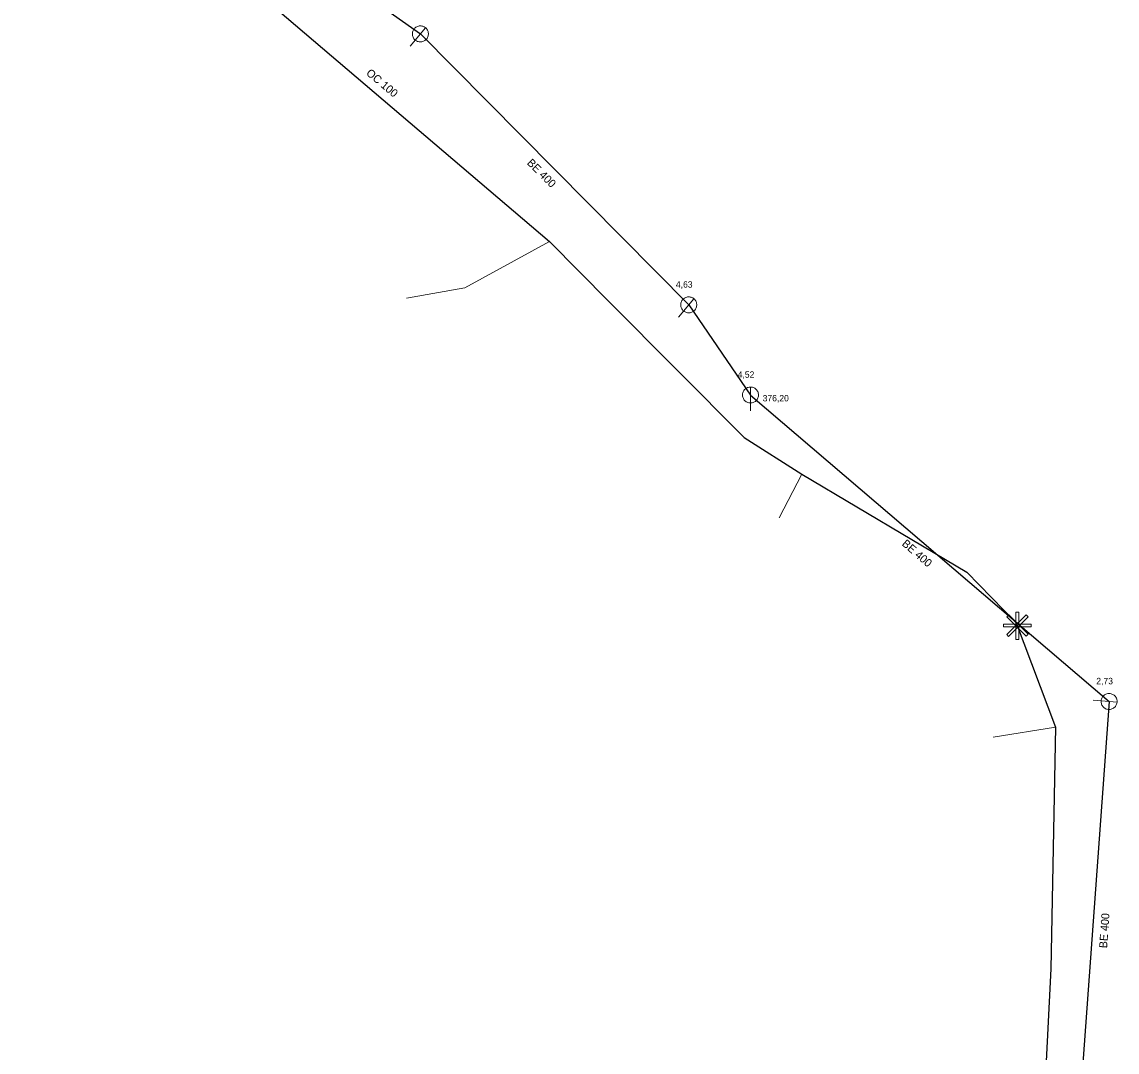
# Model space of a CAD drawing. Extents: x -809028 to -807737, y -990545 to -989489.
# Drawn here: x -808473.6 to -808336.8, y -990207.9 to -990079 of the extents above; entities that cross this region are included whole.
import ezdxf

# ---------------------------------------------------------------- set-up
doc = ezdxf.new("R2010")
doc.units = 0
doc.header["$LTSCALE"] = 0.32
for name, color, linetype, lineweight in [('1', 7, 'Continuous', 13), ('12', 7, 'Continuous', 13), ('13', 7, 'Continuous', 13), ('14', 7, 'Continuous', 25), ('17', 7, 'Continuous', 25), ('22', 7, 'Continuous', 13)]:
    doc.layers.add(name, color=color, linetype=linetype, lineweight=lineweight)

msp = doc.modelspace()

# ---------------------------------------------------------------- linework, layer by layer
at = {"layer": '12'}
for points in [[(-808348.121, -990153.189), (-808347.873, -990153.437), (-808350.302, -990155.866), (-808350.549, -990155.618)], [(-808350.54, -990153.428), (-808350.293, -990153.18), (-808347.864, -990155.609), (-808348.111, -990155.857)], [(-808349.387, -990152.825), (-808349.037, -990152.825), (-808349.037, -990156.26), (-808349.387, -990156.26)], [(-808347.503, -990154.334), (-808347.503, -990154.684), (-808350.938, -990154.684), (-808350.938, -990154.334)]]:
    msp.add_lwpolyline(points, close=True, dxfattribs=at)
at = {"layer": '13'}
for p, q in [((-808376.145, -990135.581), (-808379.004, -990141.028)), ((-808344.447, -990167.226), (-808352.252, -990168.485))]:
    msp.add_line(p, q, dxfattribs=at)
msp.add_lwpolyline([(-808407.697, -990106.489), (-808418.272, -990112.293), (-808425.572, -990113.592)], dxfattribs=at)
at = {"layer": '14'}
for p, q in [((-808423.829, -990080.539), (-808390.289, -990114.42)), ((-808337.75, -990164.01), (-808341.785, -990219.498))]:
    msp.add_line(p, q, dxfattribs=at)
for points in [[(-808473.629, -990044.855), (-808466.725, -990050.28), (-808423.829, -990080.539)], [(-808390.289, -990114.42), (-808382.57, -990125.69), (-808337.75, -990164.01)]]:
    msp.add_lwpolyline(points, dxfattribs=at)
at = {"layer": '17'}
msp.add_lwpolyline([(-808450.392, -990070.058), (-808407.697, -990106.489), (-808400.245, -990114.046), (-808383.377, -990131.011), (-808376.145, -990135.581), (-808355.548, -990147.837), (-808349.357, -990154.173), (-808344.447, -990167.226), (-808345.032, -990197.443), (-808345.713, -990210.651)], dxfattribs=at)
at = {"layer": '22'}
for p, q in [((-808425.116, -990082.069), (-808423.185, -990079.774)), ((-808391.577, -990115.95), (-808389.645, -990113.655)), ((-808382.57, -990127.69), (-808382.569, -990124.69)), ((-808339.744, -990163.858), (-808336.753, -990164.085))]:
    msp.add_line(p, q, dxfattribs=at)
for points in [[(-808423.064, -990081.183), (-808422.998, -990081.095), (-808422.942, -990081.001), (-808422.897, -990080.901), (-808422.863, -990080.798), (-808422.84, -990080.69), (-808422.829, -990080.581), (-808422.831, -990080.471), (-808422.845, -990080.363), (-808422.87, -990080.256), (-808422.906, -990080.153), (-808422.954, -990080.055), (-808423.013, -990079.962), (-808423.08, -990079.876), (-808423.157, -990079.798), (-808423.243, -990079.729), (-808423.335, -990079.67), (-808423.433, -990079.62), (-808423.535, -990079.582), (-808423.642, -990079.557), (-808423.749, -990079.542), (-808423.86, -990079.539), (-808423.968, -990079.549), (-808424.076, -990079.57), (-808424.181, -990079.603), (-808424.281, -990079.647), (-808424.375, -990079.702), (-808424.464, -990079.767), (-808424.544, -990079.84), (-808424.616, -990079.923), (-808424.679, -990080.013), (-808424.732, -990080.109), (-808424.773, -990080.21), (-808424.803, -990080.315), (-808424.823, -990080.423), (-808424.829, -990080.533), (-808424.824, -990080.642), (-808424.806, -990080.75), (-808424.777, -990080.856), (-808424.737, -990080.957), (-808424.686, -990081.054), (-808424.625, -990081.145), (-808424.554, -990081.228), (-808424.473, -990081.303), (-808424.386, -990081.369), (-808424.292, -990081.425), (-808424.193, -990081.47), (-808424.088, -990081.504), (-808423.981, -990081.527), (-808423.872, -990081.538), (-808423.763, -990081.537), (-808423.654, -990081.524), (-808423.547, -990081.498), (-808423.444, -990081.462), (-808423.346, -990081.414), (-808423.253, -990081.357), (-808423.167, -990081.288), (-808423.089, -990081.211)], [(-808389.524, -990115.064), (-808389.458, -990114.976), (-808389.402, -990114.882), (-808389.357, -990114.782), (-808389.323, -990114.679), (-808389.3, -990114.571), (-808389.289, -990114.462), (-808389.291, -990114.352), (-808389.305, -990114.244), (-808389.329, -990114.137), (-808389.366, -990114.035), (-808389.414, -990113.936), (-808389.473, -990113.843), (-808389.54, -990113.757), (-808389.617, -990113.679), (-808389.703, -990113.61), (-808389.794, -990113.551), (-808389.892, -990113.501), (-808389.995, -990113.463), (-808390.102, -990113.438), (-808390.209, -990113.423), (-808390.32, -990113.42), (-808390.428, -990113.43), (-808390.536, -990113.451), (-808390.641, -990113.484), (-808390.74, -990113.528), (-808390.835, -990113.583), (-808390.924, -990113.648), (-808391.004, -990113.721), (-808391.076, -990113.804), (-808391.139, -990113.894), (-808391.192, -990113.989), (-808391.233, -990114.091), (-808391.263, -990114.196), (-808391.282, -990114.304), (-808391.289, -990114.414), (-808391.284, -990114.523), (-808391.266, -990114.631), (-808391.237, -990114.736), (-808391.197, -990114.838), (-808391.146, -990114.935), (-808391.085, -990115.026), (-808391.014, -990115.109), (-808390.933, -990115.184), (-808390.846, -990115.25), (-808390.752, -990115.306), (-808390.653, -990115.351), (-808390.548, -990115.385), (-808390.441, -990115.408), (-808390.332, -990115.419), (-808390.223, -990115.418), (-808390.114, -990115.405), (-808390.008, -990115.379), (-808389.904, -990115.343), (-808389.806, -990115.295), (-808389.713, -990115.238), (-808389.627, -990115.169), (-808389.549, -990115.092)], [(-808381.57, -990125.69), (-808381.575, -990125.581), (-808381.593, -990125.473), (-808381.623, -990125.367), (-808381.663, -990125.266), (-808381.715, -990125.169), (-808381.777, -990125.079), (-808381.849, -990124.996), (-808381.929, -990124.922), (-808382.017, -990124.856), (-808382.111, -990124.801), (-808382.211, -990124.756), (-808382.316, -990124.723), (-808382.423, -990124.701), (-808382.532, -990124.691), (-808382.642, -990124.693), (-808382.75, -990124.707), (-808382.857, -990124.732), (-808382.96, -990124.769), (-808383.058, -990124.818), (-808383.15, -990124.876), (-808383.236, -990124.945), (-808383.313, -990125.022), (-808383.382, -990125.108), (-808383.441, -990125.2), (-808383.489, -990125.298), (-808383.526, -990125.401), (-808383.552, -990125.508), (-808383.566, -990125.616), (-808383.569, -990125.726), (-808383.559, -990125.835), (-808383.538, -990125.942), (-808383.504, -990126.046), (-808383.46, -990126.146), (-808383.405, -990126.241), (-808383.339, -990126.329), (-808383.265, -990126.409), (-808383.182, -990126.481), (-808383.092, -990126.543), (-808382.996, -990126.595), (-808382.894, -990126.636), (-808382.789, -990126.666), (-808382.681, -990126.684), (-808382.571, -990126.69), (-808382.462, -990126.684), (-808382.354, -990126.666), (-808382.249, -990126.637), (-808382.147, -990126.596), (-808382.05, -990126.544), (-808381.96, -990126.482), (-808381.877, -990126.411), (-808381.802, -990126.331), (-808381.737, -990126.243), (-808381.681, -990126.149), (-808381.637, -990126.049), (-808381.603, -990125.945), (-808381.581, -990125.837), (-808381.571, -990125.728)], [(-808337.826, -990165.007), (-808337.716, -990165.009), (-808337.607, -990164.999), (-808337.499, -990164.977), (-808337.396, -990164.945), (-808337.295, -990164.9), (-808337.201, -990164.845), (-808337.112, -990164.78), (-808337.033, -990164.706), (-808336.96, -990164.623), (-808336.898, -990164.533), (-808336.846, -990164.437), (-808336.805, -990164.335), (-808336.775, -990164.23), (-808336.757, -990164.122), (-808336.75, -990164.012), (-808336.756, -990163.903), (-808336.773, -990163.795), (-808336.802, -990163.689), (-808336.844, -990163.588), (-808336.894, -990163.492), (-808336.957, -990163.401), (-808337.028, -990163.318), (-808337.108, -990163.243), (-808337.195, -990163.177), (-808337.29, -990163.122), (-808337.389, -990163.077), (-808337.494, -990163.043), (-808337.601, -990163.021), (-808337.71, -990163.011), (-808337.82, -990163.012), (-808337.928, -990163.025), (-808338.034, -990163.051), (-808338.137, -990163.088), (-808338.236, -990163.135), (-808338.329, -990163.194), (-808338.414, -990163.262), (-808338.492, -990163.339), (-808338.561, -990163.424), (-808338.62, -990163.516), (-808338.669, -990163.615), (-808338.707, -990163.717), (-808338.733, -990163.824), (-808338.747, -990163.933), (-808338.749, -990164.042), (-808338.74, -990164.151), (-808338.719, -990164.258), (-808338.685, -990164.363), (-808338.641, -990164.463), (-808338.586, -990164.558), (-808338.521, -990164.646), (-808338.447, -990164.727), (-808338.364, -990164.798), (-808338.275, -990164.861), (-808338.179, -990164.913), (-808338.077, -990164.954), (-808337.971, -990164.985), (-808337.863, -990165.003)]]:
    msp.add_lwpolyline(points, close=True, dxfattribs=at)

# ---------------------------------------------------------------- texts
at = {"layer": '1'}
for s, rotation, p in [('OC 100', 320, (-808430.687, -990085.576)), ('BE 400', 315, (-808410.58, -990096.743)), ('BE 400', 319, (-808363.73, -990144.408)), ('BE 400', 86, (-808338.004, -990194.89))]:
    msp.add_text(s, height=1, rotation=rotation, dxfattribs=at).set_placement(p)
for s, p in [('4,63', (-808391.889, -990112.267)), ('4,52', (-808384.17, -990123.537)), ('2,73', (-808339.35, -990161.857))]:
    msp.add_text(s, height=0.8, dxfattribs=at).set_placement(p)
at = {"layer": '14'}
msp.add_text('376,20', height=0.8, dxfattribs=at).set_placement((-808381.048, -990126.49))

doc.saveas('drawing.dxf')
